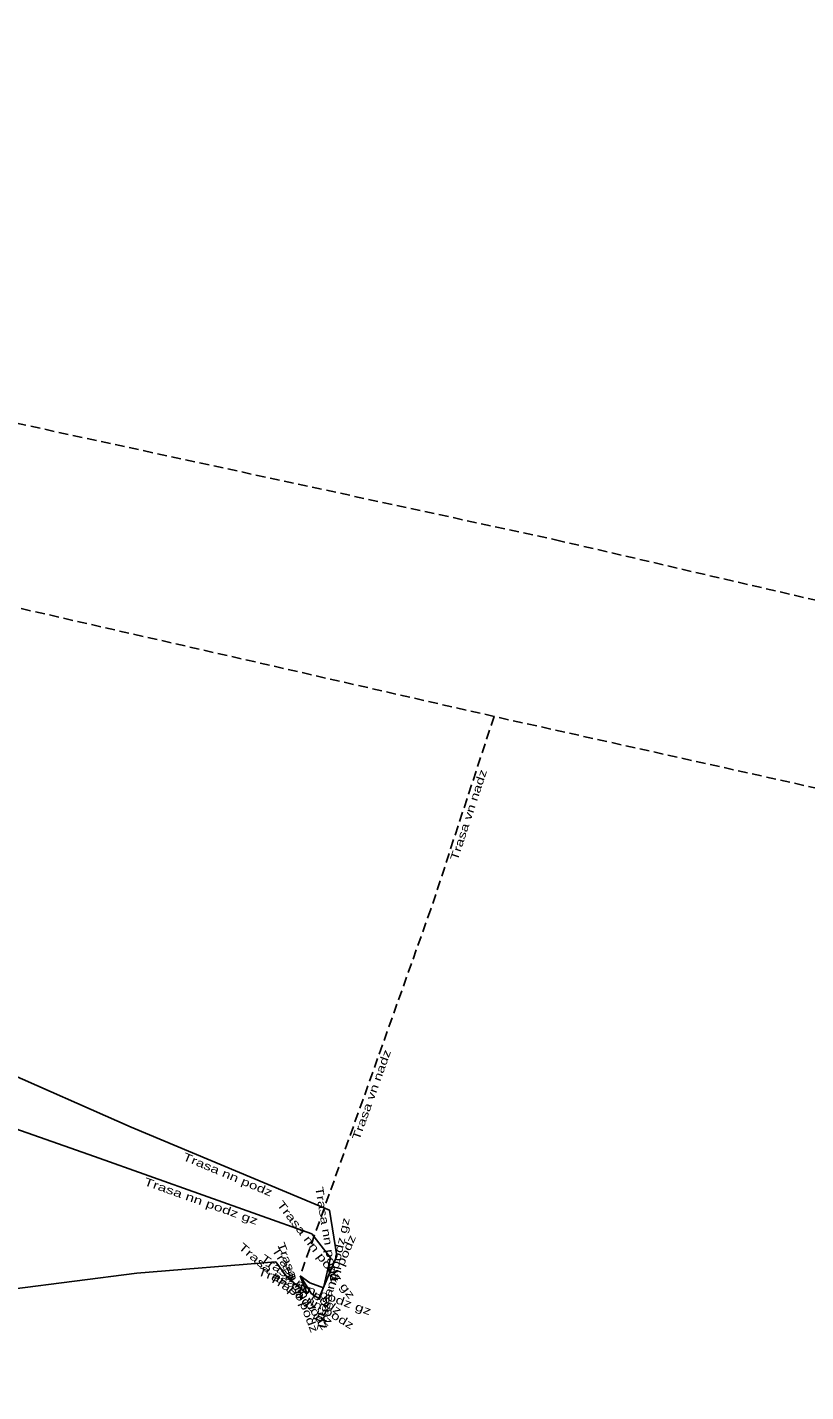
# Model space of a CAD drawing. Extents: x -648599 to -648043, y -1073975 to -1073476.
# Drawn here: x -648245.5 to -648196.9, y -1073657.6 to -1073572.4 of the extents above; entities that cross this region are included whole.
import ezdxf
from ezdxf.enums import TextEntityAlignment as Align

# ---------------------------------------------------------------- set-up
doc = ezdxf.new("R2010")
doc.units = 0
doc.header["$LTSCALE"] = 0.2
doc.linetypes.add('MEDIUM_DASHED', pattern=[4.5, 3, -1.5])
doc.layers.add('11', color=7, linetype='Continuous', lineweight=25)
doc.layers.add('21', color=7, linetype='MEDIUM_DASHED', lineweight=25)
doc.layers.add('20', color=7, linetype='Continuous')

msp = doc.modelspace()

# ---------------------------------------------------------------- linework, layer by layer
at = {"layer": '11'}
for p, q in [((-648272.2, -1073626.46), (-648239.06, -1073641.07)), ((-648241.34, -1073642.909), (-648256.47, -1073637.629)), ((-648239.06, -1073641.07), (-648226.67, -1073646.26)), ((-648227.77, -1073647.73), (-648241.34, -1073642.909)), ((-648226.67, -1073646.26), (-648226.2, -1073649.11)), ((-648226.2, -1073649.11), (-648227.33, -1073651.77)), ((-648227.89, -1073650.8), (-648228.5, -1073650.37)), ((-648228.06, -1073651.514), (-648228.5, -1073650.37)), ((-648227.791, -1073651.494), (-648228.5, -1073650.37)), ((-648227.89, -1073650.8), (-648227.03, -1073651.11)), ((-648227.33, -1073651.77), (-648227.791, -1073651.494))]:
    msp.add_line(p, q, dxfattribs=at)
for points in [[(-648227.03, -1073651.11), (-648226.61, -1073649.24), (-648227.77, -1073647.73)], [(-648230.02, -1073649.48), (-648238.7, -1073650.2), (-648250.4, -1073651.7), (-648257.6, -1073652.3), (-648285.5, -1073657.6), (-648294.9, -1073652.8), (-648298, -1073651.399), (-648307.5, -1073650.6), (-648329.2, -1073651.7), (-648340.6, -1073650.899), (-648350.3, -1073650.6)], [(-648230.02, -1073649.48), (-648229.33, -1073650.419), (-648228.06, -1073651.514)]]:
    msp.add_lwpolyline(points, dxfattribs=at)
at = {"layer": '21'}
for p, q in [((-648360.571, -1073572.382), (-648212.537, -1073604.395)), ((-648212.537, -1073604.395), (-648042.645, -1073643.821)), ((-648216.38, -1073615.425), (-648220.334, -1073627.467)), ((-648220.334, -1073627.467), (-648228.503, -1073650.365))]:
    msp.add_line(p, q, dxfattribs=at)
msp.add_lwpolyline([(-648045.041, -1073653.534), (-648216.38, -1073615.425), (-648377.485, -1073578.688)], dxfattribs=at)

# ---------------------------------------------------------------- texts
at = {"layer": '20'}
for s, rotation, width, p in [('Trasa vn nadz', 71.822, 1.4, (-648217.7394, -1073621.6485)), ('Trasa vn nadz', 70.366, 1.4, (-648223.8058, -1073639.1335)), ('Trasa nn podz', 337.272, 1.4, (-648233.1161, -1073644.2647)), ('Trasa nn podz gz', 340.445, 1.45, (-648234.7722, -1073645.9324)), ('Trasa nn podz', 279.364, 1.4, (-648227.0765, -1073647.7908)), ('Trasa nn podz gz', 307.532, 1.45, (-648227.7044, -1073648.8812)), ('Trasa nn podz gz', 77.341, 1.4, (-648226.1852, -1073650.3173)), ('Trasa nn podz', 66.984, 1.4, (-648226.1667, -1073650.6932)), ('Trasa nn podz gz', 319.232, 1.45, (-648229.5607, -1073651.0785)), ('Trasa nn podz', 302.243, 1.4, (-648228.6947, -1073651.2781)), ('Trasa nn podz', 291.021, 1.4, (-648228.8852, -1073651.1758)), ('Trasa nn podz', 324.819, 1.4, (-648228.5685, -1073651.1163)), ('Trasa nn podz gz', 340.178, 1.45, (-648227.6803, -1073651.5655)), ('Trasa nn podz', 329.091, 1.4, (-648227.8939, -1073652.1887))]:
    msp.add_text(s, height=0.5, rotation=rotation, dxfattribs=dict(at, width=width)).set_placement(p, align=Align.CENTER)

doc.saveas('drawing.dxf')
